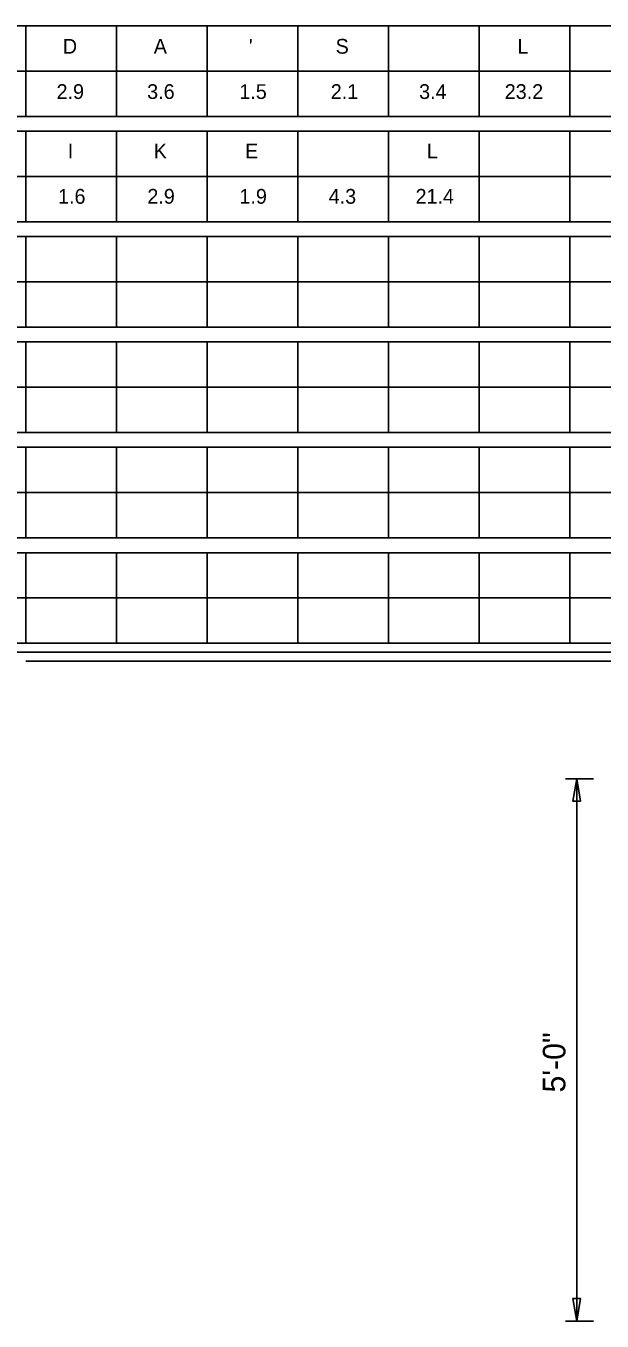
# Model space of a CAD drawing. Extents: x 17890628 to 17890844, y 17897693 to 17898031.
# Drawn here: x 17890726.43 to 17890743.43, y 17897937.64 to 17897975.84 of the extents above; entities that cross this region are included whole.
import ezdxf

# ---------------------------------------------------------------- set-up
doc = ezdxf.new("R2010")
doc.units = 0
for name, color, linetype in [('GSDims', 7, 'Continuous'), ('GSSign', 7, 'Continuous'), ('SheetLinesMisc2_dp', 7, 'Continuous')]:
    doc.layers.add(name, color=color, linetype=linetype)

msp = doc.modelspace()

# ---------------------------------------------------------------- linework, layer by layer
at = {"layer": 'GSDims'}
for p, q in [((17890743.183, 17897953.637), (17890742.35, 17897953.637)), ((17890742.683, 17897937.637), (17890742.683, 17897953.637)), ((17890743.183, 17897937.637), (17890742.35, 17897937.637))]:
    msp.add_line(p, q, dxfattribs=at)
for points in [[(17890742.683, 17897953.637), (17890742.795, 17897952.971), (17890742.572, 17897952.971)], [(17890742.683, 17897937.637), (17890742.795, 17897938.304), (17890742.572, 17897938.304)]]:
    msp.add_lwpolyline(points, close=True, dxfattribs=at)
at = {"layer": 'SheetLinesMisc2_dp'}
for p, q in [((17890706.142, 17897975.843), (17890771.912, 17897975.843)), ((17890726.429, 17897975.843), (17890726.429, 17897973.171)), ((17890729.104, 17897975.843), (17890729.104, 17897973.171)), ((17890731.779, 17897975.843), (17890731.779, 17897973.171)), ((17890734.455, 17897975.843), (17890734.455, 17897973.171)), ((17890737.131, 17897975.843), (17890737.131, 17897973.171)), ((17890739.806, 17897975.843), (17890739.806, 17897973.171)), ((17890742.481, 17897975.843), (17890742.481, 17897973.171)), ((17890706.142, 17897974.507), (17890771.912, 17897974.507)), ((17890706.142, 17897973.171), (17890771.912, 17897973.171)), ((17890706.142, 17897972.735), (17890771.912, 17897972.735)), ((17890726.429, 17897972.735), (17890726.429, 17897970.064)), ((17890729.104, 17897972.735), (17890729.104, 17897970.064)), ((17890731.779, 17897972.735), (17890731.779, 17897970.064)), ((17890734.455, 17897972.735), (17890734.455, 17897970.064)), ((17890737.131, 17897972.735), (17890737.131, 17897970.064)), ((17890739.806, 17897972.735), (17890739.806, 17897970.064)), ((17890742.481, 17897972.735), (17890742.481, 17897970.064)), ((17890706.142, 17897971.399), (17890771.912, 17897971.4)), ((17890706.142, 17897970.064), (17890771.912, 17897970.064)), ((17890706.142, 17897969.628), (17890771.912, 17897969.628)), ((17890726.429, 17897969.628), (17890726.429, 17897966.956)), ((17890729.104, 17897969.628), (17890729.104, 17897966.956)), ((17890731.779, 17897969.628), (17890731.779, 17897966.956)), ((17890734.455, 17897969.628), (17890734.455, 17897966.956)), ((17890737.131, 17897969.628), (17890737.131, 17897966.956)), ((17890739.806, 17897969.628), (17890739.806, 17897966.956)), ((17890742.481, 17897969.628), (17890742.481, 17897966.956)), ((17890706.142, 17897968.292), (17890771.912, 17897968.292)), ((17890706.142, 17897966.956), (17890771.912, 17897966.956)), ((17890706.142, 17897966.52), (17890771.912, 17897966.52)), ((17890726.429, 17897966.52), (17890726.429, 17897963.848)), ((17890729.104, 17897966.52), (17890729.104, 17897963.848)), ((17890731.779, 17897966.52), (17890731.779, 17897963.848)), ((17890734.455, 17897966.52), (17890734.455, 17897963.848)), ((17890737.131, 17897966.52), (17890737.131, 17897963.848)), ((17890739.806, 17897966.52), (17890739.806, 17897963.848)), ((17890742.481, 17897966.52), (17890742.481, 17897963.848)), ((17890706.142, 17897965.184), (17890771.912, 17897965.184)), ((17890706.142, 17897963.848), (17890771.912, 17897963.848)), ((17890706.142, 17897963.412), (17890771.912, 17897963.412)), ((17890726.429, 17897963.412), (17890726.429, 17897960.74)), ((17890729.104, 17897963.412), (17890729.104, 17897960.74)), ((17890731.779, 17897963.412), (17890731.779, 17897960.74)), ((17890734.455, 17897963.412), (17890734.455, 17897960.74)), ((17890737.131, 17897963.412), (17890737.131, 17897960.74)), ((17890739.806, 17897963.412), (17890739.806, 17897960.74)), ((17890742.481, 17897963.412), (17890742.481, 17897960.74)), ((17890706.142, 17897962.076), (17890771.912, 17897962.076)), ((17890706.142, 17897960.74), (17890771.912, 17897960.74)), ((17890706.142, 17897960.304), (17890771.912, 17897960.304)), ((17890726.429, 17897960.304), (17890726.429, 17897957.633)), ((17890729.104, 17897960.304), (17890729.104, 17897957.633)), ((17890731.779, 17897960.304), (17890731.779, 17897957.633)), ((17890734.455, 17897960.304), (17890734.455, 17897957.633)), ((17890737.131, 17897960.304), (17890737.131, 17897957.633)), ((17890739.806, 17897960.304), (17890739.806, 17897957.633)), ((17890742.481, 17897960.304), (17890742.481, 17897957.633)), ((17890706.142, 17897958.969), (17890771.912, 17897958.969)), ((17890705.5, 17897957.37), (17890839.233, 17897957.37)), ((17890706.142, 17897957.633), (17890771.912, 17897957.633)), ((17890726.429, 17897957.108), (17890771.912, 17897957.108))]:
    msp.add_line(p, q, dxfattribs=at)

# ---------------------------------------------------------------- texts
at = {"layer": 'GSDims'}
msp.add_text('5\'-0"', height=0.6667, rotation=90, dxfattribs=at).set_placement((17890742.35, 17897944.38))
at = {"layer": 'GSSign'}
for s, height, p in [('D', 0.436, (17890727.519, 17897975.024)), ('A', 0.436, (17890730.202, 17897975.024)), ("'", 0.436, (17890733.009, 17897975.024)), ('S', 0.436, (17890735.569, 17897975.024)), ('L', 0.436, (17890740.933, 17897975.024)), ('2.9', 0.4357, (17890727.334, 17897973.688)), ('3.6', 0.4357, (17890730.008, 17897973.688)), ('1.5', 0.4357, (17890732.728, 17897973.688)), ('2.1', 0.4357, (17890735.426, 17897973.688)), ('3.4', 0.4357, (17890738.033, 17897973.688)), ('23.2', 0.4357, (17890740.56, 17897973.688)), ('I', 0.436, (17890727.663, 17897971.935)), ('K', 0.436, (17890730.201, 17897971.935)), ('E', 0.436, (17890732.897, 17897971.935)), ('L', 0.436, (17890738.261, 17897971.935)), ('1.6', 0.4357, (17890727.378, 17897970.598)), ('2.9', 0.4357, (17890730.013, 17897970.598)), ('1.9', 0.4357, (17890732.731, 17897970.598)), ('4.3', 0.4357, (17890735.365, 17897970.598)), ('21.4', 0.4357, (17890737.928, 17897970.598))]:
    msp.add_text(s, height=height, dxfattribs=at).set_placement(p)

doc.saveas('drawing.dxf')
